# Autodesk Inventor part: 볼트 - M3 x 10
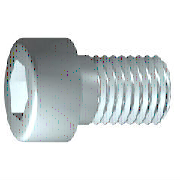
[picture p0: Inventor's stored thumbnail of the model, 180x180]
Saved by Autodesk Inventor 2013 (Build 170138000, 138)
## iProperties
Created: 2012-02
Part Number: 볼트 - M3 x 10
Material: 스테인리스강
Description: 6각 소켓 머리 캡 나사
Document SubType Name: Modeling
Standard: ISO 4762
Designer: mduedu
Standard Revision: Fourth edition 2004-03-01
Standards Organization: ISO
Language: ko-KR
Size Designation: M3 x 10
Categories: <MemberInstance><Categories><Category DisplayName="조임쇠" InternalName="e4da775c-781d-43d5-af7c-5136215cf5a6" Mnemonic="FSTN"><Category DisplayName="볼트" InternalN
Density: 7.75 g/cm^3
IsCustomPart: 0
Author: mduedu
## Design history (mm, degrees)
sketch "스케치1"
  geometry: L1 (-0.867, 0)-(10, 0); L2 (10, 0)-(10, 1.5); L3 (10, 1.5)-(1.25, 1.5); L4 (1.25, 1.5)-(0.943, 1.5); L5 (0.943, 1.5)-(0, 1.5); L6 (0, 1.5)-(0, 2.75); L7 (0, 2.75)-(-3, 2.75); L8 (-3, 2.75)-(-3, 1.443); L9 (-3, 1.443)-(-1.7, 1.443); L10 (-1.7, 1.443)-(-0.867, 0); L11 (-5.6, 0)-(12.6, 0) reference; L12 (0, -0.55)-(0, 3.3) reference; L13 (1.25, 1.5)-(0, 1.5)
  constraints: 22 end point, 6 parallel, 2 collinear, 2 perpendicular, 1 horizontal, 1 point on line
  dimensions: "d1" = 8.75 distance from line of L3.end L2 (= GEL); "d2" = 0.30683 distance of L4.end L3.end (computed from GAL); "d3" = 3 distance between parallel lines of L8 L6 (= KOH); "d4" = 1.3 distance of L8.end L9.end (= INTI); "d5" = 60 deg angle of L10 L1; "d6" = 3 diameter of L3 L1 (= GD); "d7" = 3 diameter of L5 L1 (= BDM); "d8" = 2.88675 diameter of L9 L1 (= 1.1547 x SW); "d9" = 5.5 diameter of L7 L1 (= KOD); "d26" = 10 distance between parallel lines of L12 L2 (= NLG)
revolve "본체" sketch "스케치1" stored, may be unused: angle "d10" = 90 deg
sketch "스케치2"
  geometry: L1 (0, -3.85)-(0, 3.85) reference; L2 (-3.85, 0)-(3.85, 0) reference; L3 (1.443, 0)-(0.722, -1.25); L4 (0.722, -1.25)-(-0.722, -1.25); L5 (-0.722, -1.25)-(-1.443, 0); L6 (-1.443, 0)-(-0.722, 1.25); L7 (-0.722, 1.25)-(0.722, 1.25); L8 (0.722, 1.25)-(1.443, 0); 2 further points
  constraints: 12 end point, 1 coincident, 1 horizontal alignment, 1 point on line, 12 other
extrude "슬롯" join sketch "스케치2" stored distance "d11" = 10; taper "d12" = 0 deg
workplane "Work Plane1"
fillet "Fillet2" dims "d30" = 0.1 (= R)
body "Solid1"
fillet "모깎기1" dims "d17" = 0.3 (= RR)
feature "스레드" dims "d13" = 8.75 (= GEL), "d14" = 0
chamfer "모따기1" distance "d15" = 0.30673 (= -0.5 x SPD + 0.5 x GD); stored, may be unused: second distance "d16" = 0.30673 (= GUL), angle "d27" = 45 deg
other parameters: "GD" = 3 [user parameter; used in 2 equation terms], "NLG" = 10 [user parameter; used in 1 equation term], "GEL" = 8.75 [user parameter; used in 2 equation terms], "KOD" = 5.5 [user parameter; used in 1 equation term], "KOH" = 3 [user parameter; used in 1 equation term], "INTI" = 1.3 [user parameter; used in 1 equation term], "GAL" = 0.30673 (= 0.61345 x PTC) [user parameter; used in 1 equation term], "GUL" = 0.30673 (= 0.61345 x PTC) [user parameter; used in 1 equation term], "BDM" = 3 (= NND) [user parameter; used in 1 equation term], "SW" = 2.5 [user parameter; used in 2 equation terms], "RR" = 0.3 [user parameter; used in 1 equation term], "SPD" = 2.38655 (= NND - 1.2269 x PTC) [user parameter; used in 1 equation term], "d19" = 0, "d28" = 0, "d29" = 0, "R" = 0.1 [user parameter; used in 1 equation term], "TOA" = 30 deg [user parameter], "GD1" = 2.38655 (= THREADDIA - 1.2269 x PTC) [user parameter], "THREADDIA" = 3 [user parameter; used in 1 equation term], "FAWI" = 45 deg [user parameter], "PTC" = 0.5 [user parameter; used in 5 equation terms], "NND" = 3 [user parameter; used in 2 equation terms], "E0" = 2.8875 (= 1.155 x SW) [user parameter]
